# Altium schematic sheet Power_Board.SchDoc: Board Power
size A4; Date: Not used; ApprovedBy: Not used; CheckedBy: Not used; Author: Not used; CompanyName: STMicroelectronics; DrawnBy: Not used; Engineer: Not used; Organization: Not used; Address1: Not used; Address2: Not used; Address3: Not used; Address4: Not used; DocumentNumber: Not used; Revision: Not used; SheetNumber: 20; SheetTotal: 23
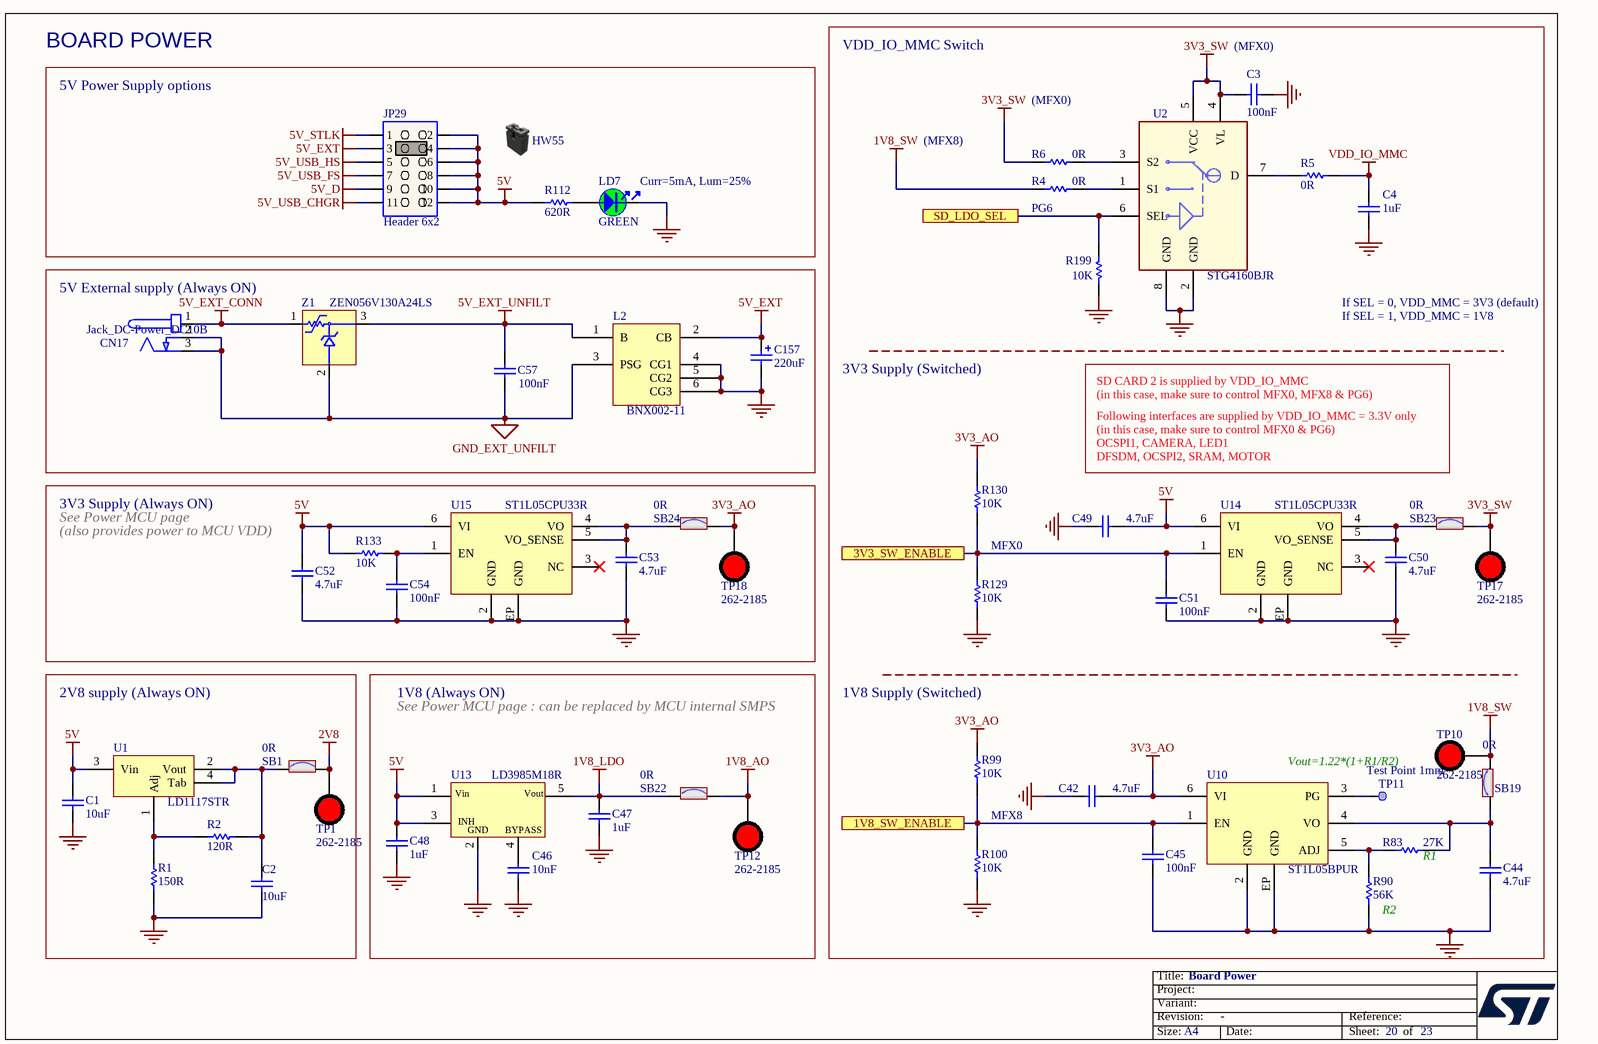
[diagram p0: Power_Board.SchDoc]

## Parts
C1  value 10uF  [C0603]  (hidden comment: Capacitor)
C2  value 10uF  [C0603]  (hidden comment: Capacitor)
C3  value 100nF  [C0402]  (hidden comment: Capacitor)
C4  value 1uF  [C0603]  (hidden comment: Capacitor)
C42  value 4.7uF  [C0603]  (hidden comment: Capacitor)
C44  value 4.7uF  [C0603]  (hidden comment: Capacitor)
C45  value 100nF  [C0402]  (hidden comment: Capacitor)
C46  value 10nF  [C0402]  (hidden comment: Capacitor)
C47  value 1uF  [C0402]  (hidden comment: Capacitor)
C48  value 1uF  [C0402]  (hidden comment: Capacitor)
C49  value 4.7uF  [C0603]  (hidden comment: Capacitor)
C50  value 4.7uF  [C0603]  (hidden comment: Capacitor)
C51  value 100nF  [C0402]  (hidden comment: Capacitor)
C52  value 4.7uF  [C0603]  (hidden comment: Capacitor)
C53  value 4.7uF  [C0603]  (hidden comment: Capacitor)
C54  value 100nF  [C0402]  (hidden comment: Capacitor)
C57  value 100nF  [C0402]  (hidden comment: Capacitor)
C157  value 220uF  [CPOL_TAJ-C_2312_H2P6]  (hidden comment: Cap_POL_TANA)
CN17  value Jack_DC-Power_DC10B  [CON_DC-POWER-SOCKET_CLIFF_FC68149_DC10B]  (hidden comment: Power_Jack_DC10B)
HW55  Shunt Black 2.54mm  (value not drawn)  (mechanical)
JP29  value Header 6x2  [CON_SAMTEC_TSW-106-07-X-D]  (hidden comment: Jumper_Header 6x2 Fitted 3-4)
L2  value BNX002-11  [FIL_MURATA_BNX002-01]  (hidden comment: BNX002-01)
LD7  value GREEN  [LED_0603_OSRAM_LG-Q396-PS-35_GREEN_1A2K_H0P4]  (hidden comment: LED_green)
R1  value 150R  [R0603]  (hidden comment: Resistor)
R2  value 120R  [R0603]  (hidden comment: Resistor)
R4  value 0R  [R0603]  (hidden comment: Resistor)
R5  value 0R  [R0603]  (hidden comment: Resistor)
R6  value 0R  [R0603]  (hidden comment: Resistor)
R83  value 27K  [R0402]  (hidden comment: Resistor)
R90  value 56K  [R0402]  (hidden comment: Resistor)
R99  value 10K  [R0402]  (hidden comment: Resistor)
R100  value 10K  [R0402]  (hidden comment: Resistor)
R112  value 620R  [R0402]  (hidden comment: Resistor)
R129  value 10K  [R0402]  (hidden comment: Resistor)
R130  value 10K  [R0402]  (hidden comment: Resistor)
R133  value 10K  [R0402]  (hidden comment: Resistor)
R199  value 10K  [R0402]  (hidden comment: Resistor)
SB1  value 0R  [SOLDER-BRIDGE_R0603-0R]  (hidden comment: SB_ON)
SB19  value 0R  [SOLDER-BRIDGE_R0603-0R]  (hidden comment: SB_ON)
SB22  value 0R  [SOLDER-BRIDGE_R0603-0R]  (hidden comment: SB_ON)
SB23  value 0R  [SOLDER-BRIDGE_R0603-0R]  (hidden comment: SB_ON)
SB24  value 0R  [SOLDER-BRIDGE_R0603-0R]  (hidden comment: SB_ON)
TP1  value 262-2185  [TP_PTH-1MM_TEST-TERMINAL_RS_262-2185_RED]  (hidden comment: Test_pin_conn_red)
TP10  value 262-2185  [TP_PTH-1MM_TEST-TERMINAL_RS_262-2185_RED]  (hidden comment: Test_pin_conn_red)
TP11  value Test Point 1mm  [TP_SMD_1MM]  (hidden comment: Test Point)  (no BOM)
TP12  value 262-2185  [TP_PTH-1MM_TEST-TERMINAL_RS_262-2185_RED]  (hidden comment: Test_pin_conn_red)
TP17  value 262-2185  [TP_PTH-1MM_TEST-TERMINAL_RS_262-2185_RED]  (hidden comment: Test_pin_conn_red)
TP18  value 262-2185  [TP_PTH-1MM_TEST-TERMINAL_RS_262-2185_RED]  (hidden comment: Test_pin_conn_red)
U1  LD1117STR  [REG_SOT223-TAB]
U2  value STG4160BJR  [ESD_FLIP-CHIP-BGA8_1P9X0P9_P050]  (hidden comment: STG4160)
U10  ST1L05BPUR  [ICC_DFN6-EPAD_3X3_P095]
U13  LD3985M18R  [REG_SOT23-5L]
U14  ST1L05CPU33R  [ICC_DFN6-EPAD_3X3_P095]
U15  ST1L05CPU33R  [ICC_DFN6-EPAD_3X3_P095]
Z1  ZEN056V130A24LS  [DIOZ_LITTELFUSE_ZEN056V130A24LS]

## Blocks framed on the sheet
BOARD POWER: HW55 JP29 LD7 R112
5V External supply (Always ON): C57 C157 CN17 L2 Z1
2V8 supply (Always ON): C1 C2 R1 R2 SB1 TP1 U1

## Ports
1V8_SW_ENABLE, 3V3_SW_ENABLE, SD_LDO_SEL

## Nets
1V8_AO: SB22.2 TP12.1
1V8_LDO: C47.2 SB22.1 U13.5(Vout)
1V8_SW: R4.1 SB19.2 TP10.1
2V8: SB1.2 TP1.1
3V3_AO: C42.1 R99.1 R130.1 SB24.2 TP18.1 U10.6(VI)
3V3_SW: C3.1 R6.1 SB23.2 TP17.1 U2.4(VL) U2.5(VCC)
5V: C1.2 C48.2 C49.1 C52.2 JP29.2 JP29.4 JP29.6 JP29.8 JP29.10 JP29.12 R112.1 R133.2 U1.3(Vin) U13.1(Vin) U13.3(CE) U14.6(VI) U15.6(VI)
5V_D: JP29.9
5V_EXT: C157.1 JP29.3 L2.2(CB)
5V_EXT_CONN: CN17.1 Z1.1
5V_EXT_UNFILT: C57.1 L2.1(B) Z1.3
5V_STLK: JP29.1
5V_USB_CHGR: JP29.11
5V_USB_FS: JP29.7
5V_USB_HS: JP29.5
GND: C1.1 C2.1 C3.2 C4.1 C42.2 C44.1 C45.2 C46.1 C47.1 C48.1 C49.2 C50.1 C51.2 C52.1 C53.1 C54.2 C157.2 L2.4(CG1) L2.5(CG2) L2.6(CG3) LD7.2 R1.1 R90.1 R100.2 R129.2 R199.1 U2.2(GND) U2.8(GND) U10.2(GND) U10.EP(GND) U13.2(GND) U14.2(GND) U14.EP(GND) U15.2(GND) U15.EP(GND)
GND_EXT_UNFILT: C57.2 CN17.2 CN17.3 L2.3(PSG) Z1.2
VDD_IO_MMC: C4.2 R5.2
1V8_SW_ENABLE: C45.1 R99.2 R100.1 U10.1(EN) ; port 1V8_SW_ENABLE
3V3_SW_ENABLE: C51.1 R129.1 R130.2 U14.1(EN) ; port 3V3_SW_ENABLE
SD_LDO_SEL: R199.2 U2.6(SEL) ; port SD_LDO_SEL
NetC2_2: C2.2 R2.1 SB1.1 U1.2(Vout) U1.4(Tab)
NetC44_2: C44.2 R83.1 SB19.1 U10.4(VO)
NetC46_2: C46.2 U13.4(BYPASS)
NetC50_2: C50.2 SB23.1 U14.4(VO) U14.5(VO_SENSE)
NetC53_2: C53.2 SB24.1 U15.4(VO) U15.5(VO_SENSE)
NetC54_1: C54.1 R133.1 U15.1(EN)
NetLD7_1: LD7.1 R112.2
NetR1_2: R1.2 R2.2 U1.1(Adj)
NetR4_2: R4.2 U2.1(S1)
NetR5_1: R5.1 U2.7(D)
NetR6_2: R6.2 U2.3(S2)
NetR83_2: R83.2 R90.2 U10.5(ADJ)
NetTP11_1: TP11.1 U10.3(PG)

Not connected (* = marked no-connect by the designer): U14 3(NC)*; U15 3(NC)*

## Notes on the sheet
- VDD_IO_MMC Switch
- (near C3) (MFX0)
- 5V Power Supply options
- (MFX0)
- (near LD7) Curr=5mA, Lum=25%
- (MFX8)
- (near R4) PG6
- If SEL = 0, VDD_MMC = 3V3 (default)
- If SEL = 1, VDD_MMC = 1V8
- 3V3 Supply (Switched)
- SD CARD 2 is supplied by VDD_IO_MMC
  (in this case, make sure to control MFX0, MFX8 & PG6)
- 3V3 Supply (Always ON)
- See Power MCU page
- Following interfaces are supplied by VDD_IO_MMC = 3.3V only
  (in this case, make sure to control MFX0 & PG6)
  OCSPI1, CAMERA, LED1
  DFSDM, OCSPI2, SRAM, MOTOR
- (near C52) (also provides power to MCU VDD)
- MFX0
- 1V8 (Always ON)
- See Power MCU page : can be replaced by MCU internal SMPS
- 1V8 Supply (Switched)
- Vout=1.22*(1+R1/R2)
- MFX8
- (near R83) R1
- (near R90) R2

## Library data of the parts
C1 C2 = MCD-00243: Capacitor, MLCC, 10uF, 6V3, X5R, 10%, 0603, T=0,8mm; Manufacturer_Part_Number: CC0603KRX5R5BB106; Manufacturer: YAGEO; Part_Preference: Recommended; Provided_By: SUBCO; ECCN_US: EAR99; ECCN_EU: NEC; Component_Country_Of_Origin: China; ID: 2626; ShowFields: YES
C3 C45 C51 C54 C57 = MCD-00006: Capacitor, MLCC, 100nF, 16V, X7R, 10%, 0402, T=0.5mm; Manufacturer_Part_Number: CC0402KRX7R7BB104; Manufacturer: YAGEO; Alternate_Manufacturer_Part_Number: GCM155R71C104KA55D; Alternate_Manufacturer: MURATA; Part_Preference: Recommended; Partial_Alternate_Internal_Part_Number: MCD-03299; Provided_By: SUBCO; ECCN_US: EAR99; ECCN_EU: NEC; Component_Country_Of_Origin: China; ID: 2474; Order_Code_RS: 9402047; ShowFields: YES
C4 = MCD-00010: Capacitor, MLCC, 1uF, 16V, X5R, 10%, 0603, T=0,8mm; Manufacturer_Part_Number: CC0603KRX5R7BB105; Manufacturer: YAGEO; Part_Preference: Recommended; Provided_By: SUBCO; ECCN_US: EAR99; ECCN_EU: NEC; Component_Country_Of_Origin: China; ID: 2470; Order_Code_RS: 2370680; ShowFields: YES
C42 C44 C50 C53 = MCD-04044: Capacitor, MLCC, 4.7uF, 10V, X5R, 20%, 0603, T=0.8mm; Manufacturer_Part_Number: C0603C475M8PAC7040; Manufacturer: KEMET CORPORATION; Part_Preference: Recommended; Component_Country_Of_Origin: Mexico; ShowFields: YES; ID: 6160
C46 = MCD-00011: Capacitor, MLCC, 10nF, 16V, X7R, 10%, 0402, T=0.5mm; Manufacturer_Part_Number: CC0402KRX7R7BB103; Manufacturer: YAGEO; Part_Preference: Recommended; Provided_By: SUBCO; ECCN_US: EAR99; ECCN_EU: NEC; Component_Country_Of_Origin: China; ID: 2469; Order_Code_RS: 3019275; ShowFields: YES
C47 C48 = MCD-00095: Capacitor, MLCC, 1uF, 6V3, X5R, 10%, 0402, T=0,5mm; Manufacturer_Part_Number: GRM155R61E105KA12; Manufacturer: MURATA; Alternate_Manufacturer_Part_Number: GRM155R60J105KE19; Part_Preference: Recommended; Provided_By: SUBCO; ECCN_US: EAR99; ECCN_EU: NEC; Component_Country_Of_Origin: Japan°°; ID: 2772; Order_Code_RS: 2218855; ShowFields: YES
C49 C52 = MCD-00097: Capacitor, MLCC, 4.7uF, 16V, X5R, 20%, 0603, T=0,8mm; Manufacturer_Part_Number: GRM188R61C475KE11; Manufacturer: MURATA; Alternate_Manufacturer_Part_Number: GRM188R61C475MAAJ; Part_Preference: Recommended; Provided_By: SUBCO; ECCN_US: EAR99; ECCN_EU: NEC; Component_Country_Of_Origin: Japan°°; ID: 2767; ShowFields: YES
C157 = MCD-00142: Capacitor, Tantalum, 220uF, 10V, 10%, 500mOhms, pkg Type_C (6032 metric), T=2.6mm; Manufacturer_Part_Number: TAJC227K010R; Manufacturer: AVX; Part_Preference: Recommended; Provided_By: SUBCO; ECCN_US: EAR99; ECCN_EU: NEC; Component_Country_Of_Origin: El Salvador; ID: 2730; Order_Code_RS: 136-4443; ShowFields: YES
CN17 = MCD-00173: DC-Power-Jack, 2.5mm, 5A, RA, TH; Manufacturer_Part_Number: DC10B; Manufacturer: CLIFF; Part_Type: Connector; BMS_Part_Number: 9087803; Part_Preference: Recommended; Provided_By: SUBCO; Component_Country_Of_Origin: Taiwan; ID: 2695; ShowFields: YES
HW55 = MCD-00043: SHUNT 2.54mm BLACK; Part_Type: Misc; Manufacturer: SAMTEC; Alternate_Manufacturer_Part_Number: 316102S111A; Alternate_Manufacturer: JIUBABA; Full_Alternate_Internal_Part_Number: MCD-02388; Manufacturer_HQ_COO: Unknown; Part_Preference: Recommended; Partial_Alternate_Internal_Part_Number: MCD-01849; Value: SNT-100-BK-G; Provided_By: SUBCO; Alternate_EMS: A; Component_Country_Of_Origin: China, Costa Rica, Malaysia, USA, Vietnam; ID: 2551; Order_Code_RS: 158-7784; ShowFields: YES
JP29 = MCD-01147: Header, 6x2, 2,54mm, VR, TH, Height 5.84mm/2.54mm - Shunt Fitted 1-2; Part_Type: Connector; Manufacturer_Part_Number: TSW-106-07-G-D; Manufacturer: SAMTEC; Part_Preference: Recommended; Provided_By: SUBCO; Component_Country_Of_Origin: China, Costa Rica, Malaysia, USA, Vietnam; ID: 3351; Order_Code_RS: 161-2280; ShowFields: YES
L2 = MCD-02155: Inductor, DC power EMI line filter, 40dB min (1MHz - 1GHz) insertion loss; Manufacturer: MURATA; Part_Preference: Recommended; Provided_By: SUBCO; Component_Country_Of_Origin: Unknown; ID: 4255; ShowFields: YES
LD7 = MCD-00588: LED Green, 0603 SMD, Forward Voltage Typ=2V, Max=2.5V; Part_Type: Display; Manufacturer_Part_Number: LG Q396-PS-35; Manufacturer: OSRAM OPTO SEMICONDUCTORS; Alternate_Manufacturer_Part_Number: VLMTG1300-GS08; Alternate_Manufacturer: VISHAY SEMICONDUCTOR OPTO DIVISION; Part_Preference: Recommended; Partial_Alternate_Internal_Part_Number: MCD-02400, MCD-03155; Provided_By: SUBCO; Component_Country_Of_Origin: Unknown; ID: 3155; ShowFields: YES
R1 = MCD-00394: Resistor,150,0603,1%,1/10W; Manufacturer_Part_Number: RC0603FR-07150RL; Manufacturer: YAGEO; Part_Preference: Recommended; Provided_By: SUBCO; ECCN_US: EAR99; ECCN_EU: NEC; Component_Country_Of_Origin: China; ID: 2879; ShowFields: YES
R2 = MCD-00338: Resistor,120R,0603,1%,1/10W; Manufacturer_Part_Number: RC0603FR-07120RL; Manufacturer: YAGEO; BMS_Part_Number: 9129734; Part_Preference: Recommended; Provided_By: SUBCO; ECCN_US: EAR99; ECCN_EU: NEC; Component_Country_Of_Origin: China; ID: 2939; ShowFields: YES
R4-R6 = MCD-00056: Resistor,0R,0603,5%,1/10W; Manufacturer_Part_Number: RC0603JR-070RL; Manufacturer: YAGEO; Part_Preference: Recommended; Provided_By: SUBCO; ECCN_US: EAR99; ECCN_EU: NEC; Component_Country_Of_Origin: China; ID: 2536; Order_Code_RS: 9233130RL; ShowFields: YES
R83 = MCD-00443: Resistor,27K,0402,1%,1/16W; Manufacturer_Part_Number: RC0402FR-0727KL; Manufacturer: YAGEO; Part_Preference: Recommended; Provided_By: SUBCO; ECCN_US: EAR99; ECCN_EU: NEC; Component_Country_Of_Origin: China; ID: 2834; ShowFields: YES
R90 = MCD-00493: Resistor,56K,0402,1%,1/16W; Manufacturer_Part_Number: RC0402FR-0756KL; Manufacturer: YAGEO; Part_Preference: Recommended; Provided_By: SUBCO; ECCN_US: EAR99; ECCN_EU: NEC; Component_Country_Of_Origin: China; ID: 2784; ShowFields: YES
R99 R100 R129 R130 R133 R199 = MCD-00053: Resistor,10K,0402,1%,1/16W; Manufacturer_Part_Number: RC0402FR-0710KL; Manufacturer: YAGEO; BMS_Part_Number: 9131590; Part_Preference: Recommended; Provided_By: SUBCO; ECCN_US: EAR99; ECCN_EU: NEC; Component_Country_Of_Origin: China; ID: 2539; Order_Code_RS: 9239359; ShowFields: YES
R112 = MCD-00499: Resistor,620R,0402,1%,1/16W; Manufacturer_Part_Number: RC0402FR-07620RL; Manufacturer: YAGEO; Part_Preference: Recommended; Provided_By: SUBCO; ECCN_US: EAR99; ECCN_EU: NEC; Component_Country_Of_Origin: China; ID: 2781; ShowFields: YES
SB1 SB19 SB22-SB24 = MCD-00071: Solder Bridge ON; Part_Type: Resistor; Manufacturer_Part_Number: RC0603JR-070RL; Manufacturer: YAGEO; Manufacturer_HQ_COO: Unknown; Part_Preference: Recommended; Provided_By: SUBCO; Component_Country_Of_Origin: China; ID: 2521; Order_Code_RS: 199-5647; ShowFields: YES
TP1 TP10 TP12 TP17 TP18 = MCD-00712: RS Pro 1mm Red Test Terminal; Part_Type: Misc; Manufacturer: RS PRO; Part_Preference: Recommended; Provided_By: SUBCO; Component_Country_Of_Origin: UK; ID: 3035; ShowFields: YES
TP11 = MCD-00074: Test Point 1mm; Part_Type: Misc; Part_Preference: Recommended; Component_Country_Of_Origin: Unknown; ID: 2518; ShowFields: YES
U1 = MCD-00721: LDO Voltage Regulator, Adjustable, 15V in, 1.1V drop, 1.25V to 15V/0.8A out, SOT-223-3; Part_Type: IC; Manufacturer: STMICROELECTRONICS; BMS_Part_Number: 9176132; Manufacturer_HQ_COO: EU; Part_Preference: Recommended; Partial_Alternate_Internal_Part_Number: MCD-02765; Provided_By: SUBCO with ST control; ECCN_US: EAR99; ECCN_EU: NEC; Component_Country_Of_Origin: China; ID: 3025; Order_Code_RS: 686-9363; ShowFields: YES
U2 = MCD-00668: Low voltage 0.5 ohm single SPDT switch with break-before-make feature and 15 kV contact ESD protection; Manufacturer: STMICROELECTRONICS; Part_Type: IC; BMS_Part_Number: 9180003; Manufacturer_HQ_COO: EU; Part_Preference: Forbidden; Provided_By: SUBCO with ST control; ECCN_US: EAR99; ECCN_EU: NEC; Component_Country_Of_Origin: Italy; ID: 3074; ShowFields: YES
U10 = MCD-00581: LDO Linear Voltage Regulator IC Positive Adjustable 1 Output Adjustable 1.3A 6-DFN (3x3); Manufacturer: STMICROELECTRONICS; BMS_Part_Number: 9176239; Manufacturer_HQ_COO: EU; Part_Preference: Recommended; Provided_By: SUBCO with ST control; ECCN_US: EAR99; ECCN_EU: NEC; Component_Country_Of_Origin: Malaysia; ID: 3163; Order_Code_RS: 188-9209; ShowFields: YES
U13 = MCD-00078: Ultra low drop-low noise BiCMOS voltage, regulators low ESR capacitors compatible; Manufacturer: STMICROELECTRONICS; Part_Type: IC; BMS_Part_Number: 9176159; Manufacturer_HQ_COO: EU; Part_Preference: Recommended; Provided_By: SUBCO with ST control; ECCN_US: EAR99; ECCN_EU: NEC; Component_Country_Of_Origin: Malaysia; ID: 2516; Order_Code_RS: 686-8830; ShowFields: YES
U14 U15 = MCD-01025: LDO, 3.3V, 1.3A, Very low quiescent current BiCMOS voltage regulator; Part_Type: IC; Manufacturer: STMICROELECTRONICS; BMS_Part_Number: 9176246; Manufacturer_HQ_COO: EU; Part_Preference: Recommended; Provided_By: SUBCO with ST control; ECCN_US: EAR99; ECCN_EU: NEC; Component_Country_Of_Origin: Malaysia; ID: 2998; ShowFields: YES
Z1 = MCD-00149: Protection circuit Zener Diode; Manufacturer: LITTELFUSE; BMS_Part_Number: 9127091; Part_Preference: Forbidden; Provided_By: SUBCO; ECCN_US: EAR99; ECCN_EU: NEC; ID: 2716; Order_Code_RS: 494-723; ShowFields: YES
